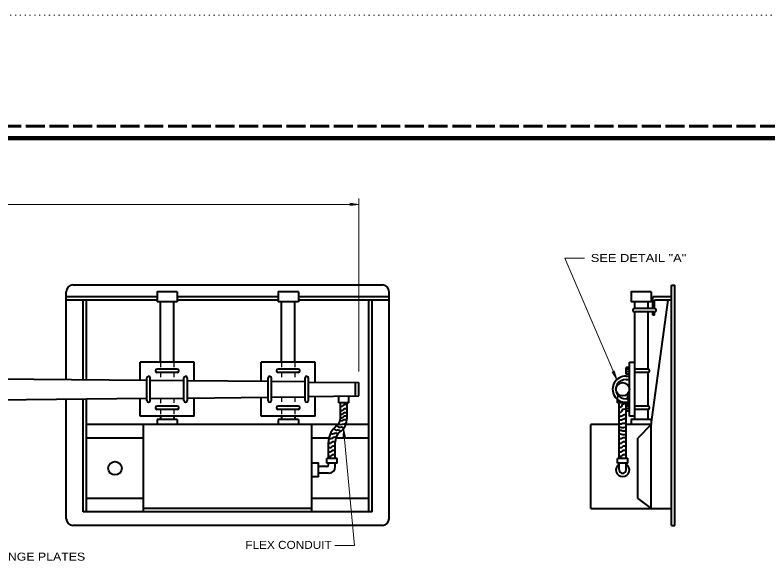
# Model space of a CAD drawing. Extents: x 312583 to 312854, y 144419 to 144597.
# Drawn here: x 312673.4 to 312744.9, y 144544.8 to 144596.8 of the extents above; entities that cross this region are included whole.
import ezdxf

# ---------------------------------------------------------------- set-up
doc = ezdxf.new("R2010")
doc.units = 0
doc.header["$LTSCALE"] = 0.3
for name, pattern in [('DOTTED', [1.5, 0.3, -1.2]), ('LONG_DASHED', [7.5, 6, -1.5]), ('SHORT_DASHED', [2.7, 1.5, -1.2])]:
    doc.linetypes.add(name, pattern=pattern)
for name, color, linetype, lineweight in [('1', 7, 'Continuous', 40), ('2', 7, 'Continuous', 13), ('62', 7, 'DOTTED', 13), ('63', 7, 'LONG_DASHED', 60)]:
    doc.layers.add(name, color=color, linetype=linetype, lineweight=lineweight)

msp = doc.modelspace()

# ---------------------------------------------------------------- linework, layer by layer
at = {"layer": '1'}
for p, q in [((312708.3057, 144571.1419), (312678.9193, 144571.1419)), ((312735.7606, 144548.3029), (312735.7606, 144571.1419)), ((312735.7606, 144571.1419), (312736.075, 144571.1419)), ((312736.075, 144548.3029), (312736.075, 144571.1419)), ((312678.283, 144562.1643), (312678.283, 144570.5056)), ((312688.8247, 144570.5056), (312688.8247, 144569.5473)), ((312700.3247, 144570.5056), (312700.3247, 144569.5473)), ((312708.9497, 144548.9393), (312708.9497, 144570.5056)), ((312733.844, 144570.5056), (312733.844, 144569.5473)), ((312686.908, 144570.0226), (312678.283, 144570.0226)), ((312686.908, 144569.7083), (312678.283, 144569.7083)), ((312679.8777, 144562.1489), (312679.8777, 144569.7083)), ((312680.1997, 144562.1489), (312680.1997, 144569.7083)), ((312688.8247, 144569.5473), (312686.908, 144569.5473)), ((312687.2223, 144563.7973), (312687.2223, 144569.5473)), ((312688.5027, 144563.7973), (312688.5027, 144569.5473)), ((312698.408, 144570.0226), (312688.8247, 144570.0226)), ((312698.408, 144569.7083), (312688.8247, 144569.7083)), ((312700.3247, 144569.5473), (312698.408, 144569.5473)), ((312698.7223, 144563.7973), (312698.7223, 144569.5473)), ((312700.0027, 144563.7973), (312700.0027, 144569.5473)), ((312708.9497, 144570.0226), (312700.3247, 144570.0226)), ((312708.9497, 144569.7083), (312700.3247, 144569.7083)), ((312707.033, 144549.5833), (312707.033, 144569.7083)), ((312707.3473, 144549.5833), (312707.3473, 144569.7083)), ((312733.844, 144569.5473), (312731.9273, 144569.5473)), ((312732.2416, 144569.5473), (312732.2416, 144568.9109)), ((312733.522, 144569.5473), (312733.522, 144568.9109)), ((312733.844, 144557.8863), (312735.4386, 144569.7083)), ((312735.7606, 144570.0226), (312733.9973, 144570.0226)), ((312733.9973, 144568.9109), (312733.9973, 144570.0226)), ((312735.7606, 144569.7083), (312734.1583, 144569.7083)), ((312734.1583, 144568.9109), (312734.1583, 144569.7083)), ((312734.1583, 144568.9109), (312732.2416, 144568.9109)), ((312732.2416, 144568.5889), (312732.2416, 144558.3693)), ((312734.1583, 144568.5889), (312732.2416, 144568.5889)), ((312733.522, 144568.5889), (312733.522, 144563.1609)), ((312733.9973, 144568.2669), (312733.9973, 144568.5889)), ((312734.1583, 144568.2669), (312733.9973, 144568.2669)), ((312734.1583, 144568.2669), (312734.1583, 144568.5889)), ((312690.4193, 144563.7973), (312685.3057, 144563.7973)), ((312685.3057, 144562.0953), (312685.3057, 144563.7973)), ((312690.4193, 144562.0723), (312690.4193, 144563.7973)), ((312701.9193, 144563.7973), (312696.8057, 144563.7973)), ((312696.8057, 144562.0033), (312696.8057, 144563.7973)), ((312701.9193, 144561.9189), (312701.9193, 144563.7973)), ((312731.7663, 144563.7973), (312732.2416, 144563.7973)), ((312688.8247, 144563.1609), (312686.908, 144563.1609)), ((312700.3247, 144563.1609), (312698.408, 144563.1609)), ((312731.4443, 144562.6779), (312731.4443, 144563.3143)), ((312731.7663, 144563.3143), (312731.4443, 144563.3143)), ((312731.7663, 144563.1073), (312731.4443, 144563.1073)), ((312733.522, 144563.1609), (312732.2416, 144563.1609)), ((312659.4307, 144562.3559), (312685.9497, 144562.0876)), ((312688.8247, 144562.8389), (312686.908, 144562.8389)), ((312700.3247, 144562.8389), (312698.408, 144562.8389)), ((312731.7663, 144562.8926), (312731.4443, 144562.8926)), ((312731.7663, 144562.6779), (312731.4443, 144562.6779)), ((312731.4443, 144562.4786), (312731.7663, 144562.4786)), ((312733.522, 144562.8389), (312732.2416, 144562.8389)), ((312733.522, 144562.8389), (312733.522, 144559.6419)), ((312685.9497, 144560.1633), (312685.9497, 144562.3176)), ((312686.264, 144560.1633), (312686.264, 144562.3176)), ((312686.264, 144562.1106), (312689.461, 144562.0799)), ((312689.461, 144560.1633), (312689.461, 144562.3176)), ((312689.783, 144560.1633), (312689.783, 144562.3176)), ((312689.783, 144562.0799), (312697.4497, 144562.0033)), ((312697.4497, 144560.1633), (312697.4497, 144562.3176)), ((312697.764, 144560.1633), (312697.764, 144562.3176)), ((312697.764, 144561.9956), (312700.961, 144561.9649)), ((312700.961, 144560.1633), (312700.961, 144562.3176)), ((312701.283, 144560.1633), (312701.283, 144562.3176)), ((312701.283, 144561.9266), (312706.0747, 144561.8806)), ((312705.7527, 144560.6003), (312705.7527, 144561.8806)), ((312706.0747, 144560.6003), (312706.0747, 144561.8806)), ((312731.4443, 144562.1566), (312731.7663, 144562.1566)), ((312659.4307, 144560.1249), (312685.9497, 144560.3933)), ((312678.283, 144548.9393), (312678.283, 144560.3166)), ((312679.8777, 144549.5833), (312679.8777, 144560.3319)), ((312680.1997, 144549.5833), (312680.1997, 144560.3396)), ((312685.3057, 144558.6836), (312685.3057, 144560.3856)), ((312686.264, 144560.3703), (312689.461, 144560.4009)), ((312689.783, 144560.4009), (312697.4497, 144560.4853)), ((312690.4193, 144558.6836), (312690.4193, 144560.4086)), ((312696.8057, 144558.6836), (312696.8057, 144560.4776)), ((312697.764, 144560.4853), (312700.961, 144560.5159)), ((312701.283, 144560.5543), (312706.0747, 144560.6003)), ((312701.9193, 144558.6836), (312701.9193, 144560.5619)), ((312704.158, 144559.9409), (312704.158, 144560.6003)), ((312705.1163, 144559.9409), (312705.1163, 144560.5926)), ((312730.647, 144560.7229), (312730.647, 144560.8226)), ((312730.647, 144559.9409), (312730.647, 144560.2629)), ((312731.7663, 144560.3243), (312731.4443, 144560.3243)), ((312731.6053, 144560.3243), (312731.6053, 144560.8226)), ((312688.8247, 144559.6419), (312686.908, 144559.6419)), ((312700.3247, 144559.6419), (312698.408, 144559.6419)), ((312705.1163, 144559.9409), (312704.158, 144559.9409)), ((312704.319, 144558.5149), (312704.319, 144559.9409)), ((312704.9553, 144558.5149), (312704.9553, 144559.9409)), ((312731.6053, 144559.9409), (312730.647, 144559.9409)), ((312730.808, 144554.6663), (312730.808, 144559.9409)), ((312731.4443, 144559.8029), (312731.4443, 144559.9409)), ((312731.4443, 144559.1666), (312731.4443, 144559.8029)), ((312731.7663, 144559.8029), (312731.4443, 144559.8029)), ((312731.7663, 144559.5883), (312731.4443, 144559.5883)), ((312731.4596, 144560.0023), (312731.7663, 144560.0023)), ((312731.6053, 144559.9409), (312731.6053, 144560.0023)), ((312733.522, 144559.6419), (312732.2416, 144559.6419)), ((312688.8247, 144559.3276), (312686.908, 144559.3276)), ((312700.3247, 144559.3276), (312698.408, 144559.3276)), ((312731.7663, 144559.3813), (312731.4443, 144559.3813)), ((312731.7663, 144559.1666), (312731.4443, 144559.1666)), ((312731.4443, 144554.6663), (312731.4443, 144559.1666)), ((312733.522, 144559.3276), (312732.2416, 144559.3276)), ((312733.522, 144559.3276), (312733.522, 144558.3693)), ((312690.4193, 144558.6836), (312685.3057, 144558.6836)), ((312688.8247, 144558.3693), (312686.908, 144558.3693)), ((312686.908, 144558.3693), (312686.908, 144557.8863)), ((312687.2223, 144558.6836), (312687.2223, 144558.3693)), ((312688.5027, 144558.6836), (312688.5027, 144558.3693)), ((312688.8247, 144558.3693), (312688.8247, 144557.8863)), ((312701.9193, 144558.6836), (312696.8057, 144558.6836)), ((312700.3247, 144558.3693), (312698.408, 144558.3693)), ((312698.408, 144558.3693), (312698.408, 144557.8863)), ((312698.7223, 144558.6836), (312698.7223, 144558.3693)), ((312700.0027, 144558.6836), (312700.0027, 144558.3693)), ((312700.3247, 144558.3693), (312700.3247, 144557.8863)), ((312732.2416, 144558.6836), (312731.7663, 144558.6836)), ((312733.844, 144558.3693), (312733.844, 144557.8863)), ((312704.1043, 144557.8863), (312680.1997, 144557.8863)), ((312685.6277, 144549.5833), (312685.6277, 144557.8863)), ((312701.5973, 144549.5833), (312701.5973, 144557.8863)), ((312703.859, 144557.6563), (312703.7823, 144557.6026)), ((312707.033, 144557.8863), (312704.8327, 144557.8863)), ((312728.094, 144549.8976), (312728.094, 144557.8863)), ((312730.808, 144557.8863), (312728.094, 144557.8863)), ((312733.844, 144557.8863), (312731.4443, 144557.8863)), ((312733.844, 144557.8863), (312732.5636, 144556.6059)), ((312733.844, 144549.8976), (312733.844, 144557.8863)), ((312685.6277, 144556.6059), (312680.1997, 144556.6059)), ((312703.2303, 144556.6059), (312701.5973, 144556.6059)), ((312703.1997, 144554.6663), (312703.1997, 144556.1996)), ((312703.836, 144554.6663), (312703.836, 144556.2226)), ((312707.033, 144556.6059), (312703.882, 144556.6059)), ((312732.5636, 144550.8559), (312732.5636, 144556.6059)), ((312703.0387, 144554.2139), (312703.0387, 144554.6663)), ((312703.997, 144554.6663), (312703.0387, 144554.6663)), ((312703.997, 144554.2139), (312703.997, 144554.6969)), ((312730.647, 144554.2139), (312730.647, 144554.6663)), ((312731.6053, 144554.6663), (312730.647, 144554.6663)), ((312731.6053, 144554.2139), (312731.6053, 144554.6969)), ((312703.0387, 144553.8919), (312702.2413, 144553.8919)), ((312703.997, 144554.2139), (312703.0387, 144554.2139)), ((312703.1997, 144554.0529), (312703.1997, 144554.2139)), ((312703.836, 144553.8919), (312703.836, 144554.2139)), ((312731.6053, 144554.2139), (312730.647, 144554.2139)), ((312730.808, 144553.5776), (312730.808, 144554.2139)), ((312730.808, 144554.0529), (312730.808, 144554.2139)), ((312731.4443, 144553.5776), (312731.4443, 144554.2139)), ((312703.1997, 144553.2556), (312702.2413, 144553.2556)), ((312702.2413, 144552.9336), (312701.5973, 144552.9336)), ((312685.6277, 144550.8559), (312680.1997, 144550.8559)), ((312707.033, 144550.8559), (312701.5973, 144550.8559)), ((312732.5636, 144550.8559), (312733.844, 144549.8976)), ((312707.3473, 144549.5833), (312679.8777, 144549.5833)), ((312701.5973, 144549.8976), (312685.6277, 144549.8976)), ((312728.094, 144549.8976), (312735.7606, 144549.8976)), ((312708.3057, 144548.3029), (312678.9193, 144548.3029)), ((312735.7606, 144548.3029), (312736.075, 144548.3029))]:
    msp.add_line(p, q, dxfattribs=at)
at = {"layer": '1', "linetype": 'SHORT_DASHED', "lineweight": 25}
for p, q in [((312687.2223, 144563.7973), (312687.2223, 144563.1609)), ((312688.5027, 144563.7973), (312688.5027, 144563.1609)), ((312698.7223, 144563.7973), (312698.7223, 144563.1609)), ((312700.0027, 144563.7973), (312700.0027, 144563.1609)), ((312687.2223, 144562.8389), (312687.2223, 144562.1029)), ((312688.5027, 144562.8389), (312688.5027, 144562.0953)), ((312698.7223, 144562.8389), (312698.7223, 144561.9879)), ((312700.0027, 144562.8389), (312700.0027, 144561.9726)), ((312687.2223, 144560.3779), (312687.2223, 144559.6419)), ((312688.5027, 144560.3933), (312688.5027, 144559.6419)), ((312698.7223, 144560.4929), (312698.7223, 144559.6419)), ((312700.0027, 144560.5083), (312700.0027, 144559.6419)), ((312730.647, 144560.7229), (312730.647, 144560.2629)), ((312731.6053, 144560.3243), (312731.6053, 144560.0023)), ((312687.2223, 144559.3276), (312687.2223, 144558.6836)), ((312688.5027, 144559.3276), (312688.5027, 144558.6836)), ((312698.7223, 144559.3276), (312698.7223, 144558.6836)), ((312700.0027, 144559.3276), (312700.0027, 144558.6836))]:
    msp.add_line(p, q, dxfattribs=at)
at = {"layer": '1', "lineweight": 158}
msp.add_lwpolyline([(312616.5, 144423.1446), (312616.5, 144585.0846), (312849, 144585.0846)], dxfattribs=at)
at = {"layer": '1'}
for points in [[(312688.8247, 144570.5056), (312686.908, 144570.5056), (312686.908, 144569.5473)], [(312700.3247, 144570.5056), (312698.408, 144570.5056), (312698.408, 144569.5473)], [(312733.844, 144570.5056), (312731.9273, 144570.5056), (312731.9273, 144569.5473)], [(312731.7663, 144558.6836), (312731.7663, 144561.2443), (312731.7663, 144563.7973)], [(312733.844, 144558.3693), (312731.9273, 144558.3693), (312731.9273, 144557.8863)], [(312704.848, 144557.9399), (312704.641, 144557.9169), (312704.48, 144557.8786), (312704.2883, 144557.8709), (312704.181, 144557.9169)], [(312702.2413, 144552.9336), (312702.2413, 144554.2139), (312701.5973, 144554.2139)]]:
    msp.add_lwpolyline(points, dxfattribs=at)
for centre in [(312731.1255, 144561.2411), (312682.9124, 144553.7341)]:
    msp.add_circle(centre, 0.6389, dxfattribs=at)
for centre, radius, start, end in [((312678.9193, 144570.505), 0.6389, 90, 180), ((312708.3082, 144570.505), 0.6389, 0, 90), ((312732.2436, 144568.748), 0.1597, 90, 270), ((312734.1602, 144568.748), 0.1597, 270, 90), ((312686.9054, 144562.998), 0.1597, 90, 270), ((312688.8221, 144562.998), 0.1597, 270, 90), ((312698.4054, 144562.998), 0.1597, 90, 270), ((312700.3221, 144562.998), 0.1597, 270, 90), ((312733.5213, 144562.998), 0.1597, 270, 90), ((312686.1068, 144562.3195), 0.1597, 0, 180), ((312689.6207, 144562.3195), 0.1597, 0, 180), ((312697.6068, 144562.3195), 0.1597, 0, 180), ((312701.1207, 144562.3195), 0.1597, 0, 180), ((312731.4058, 144561.2414), 1.2387, 87.56224, 272.43775), ((312731.4058, 144561.2414), 0.9192, 87.56224, 272.43775), ((312686.1068, 144560.1633), 0.1597, 180, 0), ((312686.9054, 144559.4841), 0.1597, 90, 270), ((312688.8221, 144559.4841), 0.1597, 270, 90), ((312689.6207, 144560.1633), 0.1597, 180, 0), ((312697.6068, 144560.1633), 0.1597, 180, 0), ((312698.4054, 144559.4841), 0.1597, 90, 270), ((312700.3221, 144559.4841), 0.1597, 270, 90), ((312701.1207, 144560.1633), 0.1597, 180, 0), ((312733.5213, 144559.4841), 0.1597, 270, 90), ((312703.2811, 144558.5177), 1.0341, 303.82272, 359.99129), ((312703.2811, 144558.5177), 1.673, 303.82272, 359.99129), ((312704.9942, 144556.2717), 1.7985, 132.38982, 182.27764), ((312704.9942, 144556.2717), 1.1596, 132.38982, 182.27764), ((312703.0374, 144554.0536), 0.1597, 270, 0), ((312703.1971, 144553.8938), 0.6389, 270, 0), ((312731.1255, 144553.5744), 0.6389, 120.00073, 60), ((312731.1255, 144553.5744), 0.3194, 180, 0), ((312678.9193, 144548.9425), 0.6389, 180, 270), ((312708.3082, 144548.9425), 0.6389, 270, 0)]:
    msp.add_arc(centre, radius, start, end, dxfattribs=at)
for points in [[(312704.9553, 144559.7493), (312704.7177, 144559.7723), (312704.6027, 144559.7109), (312704.526, 144559.6343), (312704.4493, 144559.6036), (312704.3113, 144559.6189)], [(312731.452, 144559.8796), (312731.199, 144559.8183), (312731.0916, 144559.7799), (312731.015, 144559.6113), (312730.9, 144559.5039), (312730.808, 144559.5039)], [(312704.9553, 144559.3353), (312704.7177, 144559.3659), (312704.6027, 144559.2969), (312704.526, 144559.2203), (312704.4493, 144559.1973), (312704.3113, 144559.2126)], [(312704.9553, 144558.9826), (312704.7177, 144559.0056), (312704.6027, 144558.9443), (312704.526, 144558.8676), (312704.4493, 144558.8369), (312704.3113, 144558.8523)], [(312731.4443, 144559.3813), (312731.1913, 144559.3199), (312731.084, 144559.2893), (312731.0073, 144559.1206), (312730.8923, 144559.0133), (312730.8003, 144559.0133)], [(312731.4443, 144558.8063), (312731.2756, 144558.8063), (312731.1606, 144558.7449), (312731.0456, 144558.6913), (312730.8846, 144558.6606), (312730.808, 144558.7143)], [(312704.94, 144558.3309), (312704.7483, 144558.3386), (312704.5797, 144558.2926), (312704.4493, 144558.2236), (312704.2883, 144558.2696)], [(312704.9553, 144558.6453), (312704.7177, 144558.6759), (312704.6027, 144558.6069), (312704.526, 144558.5303), (312704.4493, 144558.5073), (312704.3113, 144558.5226)], [(312731.4443, 144558.3846), (312731.291, 144558.4229), (312731.153, 144558.3539), (312731.0226, 144558.3079), (312730.8386, 144558.2849), (312730.808, 144558.2773)], [(312704.365, 144557.2423), (312704.1427, 144557.3419), (312703.9433, 144557.3343), (312703.813, 144557.3726), (312703.7057, 144557.5259)], [(312704.6487, 144557.5566), (312704.411, 144557.6256), (312704.1963, 144557.6103), (312704.0967, 144557.6793), (312703.9817, 144557.7559)], [(312731.4443, 144557.9783), (312731.2373, 144557.9859), (312731.0533, 144557.9553), (312730.946, 144557.9246), (312730.808, 144557.9553)], [(312731.4443, 144557.2806), (312731.2373, 144557.2653), (312731.0533, 144557.2959), (312730.946, 144557.3343), (312730.808, 144557.2959)], [(312731.4366, 144557.6256), (312731.2066, 144557.5873), (312731.0456, 144557.5873), (312730.8846, 144557.6103), (312730.8233, 144557.6103)], [(312703.9203, 144556.7056), (312703.698, 144556.6673), (312703.606, 144556.6213), (312703.56, 144556.5676), (312703.4067, 144556.5446), (312703.2763, 144556.5523), (312703.2303, 144556.6059)], [(312704.0583, 144556.9586), (312703.9433, 144557.0506), (312703.813, 144557.0506), (312703.6827, 144556.9893), (312703.491, 144556.9969), (312703.4373, 144557.1656)], [(312731.4366, 144556.9126), (312731.222, 144556.9049), (312731.0456, 144556.9356), (312730.9383, 144556.9663), (312730.808, 144556.9356)], [(312731.4443, 144556.5676), (312731.268, 144556.6289), (312731.107, 144556.5906), (312730.9843, 144556.5369), (312730.8923, 144556.5139), (312730.8156, 144556.5753)], [(312703.836, 144556.2226), (312703.5983, 144556.2533), (312703.491, 144556.1843), (312703.4143, 144556.1076), (312703.3377, 144556.0846), (312703.192, 144556.0999)], [(312731.4443, 144556.2226), (312731.2143, 144556.2533), (312731.0993, 144556.1843), (312731.0226, 144556.1076), (312730.946, 144556.0846), (312730.808, 144556.0999)], [(312703.8437, 144555.8009), (312703.606, 144555.8239), (312703.491, 144555.7626), (312703.4143, 144555.6859), (312703.3377, 144555.6629), (312703.1997, 144555.6706)], [(312703.8437, 144555.4023), (312703.606, 144555.4329), (312703.491, 144555.3639), (312703.4143, 144555.2873), (312703.3377, 144555.2643), (312703.1997, 144555.2796)], [(312731.452, 144555.8009), (312731.2143, 144555.8239), (312731.0993, 144555.7626), (312731.0226, 144555.6859), (312730.946, 144555.6629), (312730.808, 144555.6706)], [(312731.452, 144555.4023), (312731.2143, 144555.4329), (312731.0993, 144555.3639), (312731.0226, 144555.2873), (312730.946, 144555.2643), (312730.808, 144555.2796)], [(312703.8437, 144554.9959), (312703.606, 144555.0189), (312703.491, 144554.9576), (312703.4143, 144554.8809), (312703.3377, 144554.8579), (312703.1997, 144554.8656)], [(312731.452, 144554.9959), (312731.2143, 144555.0189), (312731.0993, 144554.9576), (312731.0226, 144554.8809), (312730.946, 144554.8579), (312730.808, 144554.8656)]]:
    msp.add_spline(points, degree=3, dxfattribs=at)
at = {"layer": '2'}
for p, q in [((312637.1207, 144578.7933), (312706.0747, 144578.7933)), ((312705.2083, 144578.9006), (312705.4843, 144578.7933)), ((312706.0747, 144578.7933), (312705.2083, 144578.9006)), ((312705.2083, 144578.9006), (312705.4843, 144578.7933)), ((312706.0747, 144578.7933), (312705.2083, 144578.9006)), ((312705.2083, 144578.6859), (312705.4843, 144578.7933)), ((312706.0747, 144578.7933), (312705.2083, 144578.6859)), ((312705.2083, 144578.6859), (312705.4843, 144578.7933)), ((312706.0747, 144578.7933), (312705.2083, 144578.6859)), ((312706.0747, 144562.9156), (312706.0747, 144579.3683)), ((312725.6253, 144573.6873), (312727.5113, 144573.6873)), ((312730.5703, 144562.1566), (312725.6253, 144573.6873)), ((312730.1256, 144562.9079), (312730.3326, 144562.6933)), ((312730.5703, 144562.1566), (312730.1256, 144562.9079)), ((312730.325, 144562.9923), (312730.3326, 144562.6933)), ((312730.5703, 144562.1566), (312730.325, 144562.9923)), ((312704.618, 144557.5106), (312704.595, 144556.6366)), ((312704.618, 144557.5106), (312704.802, 144556.6596)), ((312704.595, 144556.6366), (312704.6717, 144556.9203)), ((312704.802, 144556.6596), (312704.6717, 144556.9203))]:
    msp.add_line(p, q, dxfattribs=at)
msp.add_lwpolyline([(312703.7823, 144546.3863), (312705.6683, 144546.3863), (312704.618, 144557.5106)], dxfattribs=at)
at = {"layer": '62'}
msp.add_line((312601.2, 144596.7846), (312853.5, 144596.7846), dxfattribs=at)
at = {"layer": '63'}
msp.add_line((312851.75, 144586.2246), (312583.526, 144586.2246), dxfattribs=at)

# ---------------------------------------------------------------- texts
at = {"layer": '2'}
for s, width, p in [('SEE DETAIL "A"', 1.2, (312728.0975, 144573.3298)), ('FLEX CONDUIT', 1.1, (312695.2926, 144546.0748)), ('32 MM THK FLANGE PLATES', 1.15, (312664.0397, 144544.9574))]:
    msp.add_text(s, height=0.76, dxfattribs=dict(at, width=width)).set_placement(p)

doc.saveas('drawing.dxf')
